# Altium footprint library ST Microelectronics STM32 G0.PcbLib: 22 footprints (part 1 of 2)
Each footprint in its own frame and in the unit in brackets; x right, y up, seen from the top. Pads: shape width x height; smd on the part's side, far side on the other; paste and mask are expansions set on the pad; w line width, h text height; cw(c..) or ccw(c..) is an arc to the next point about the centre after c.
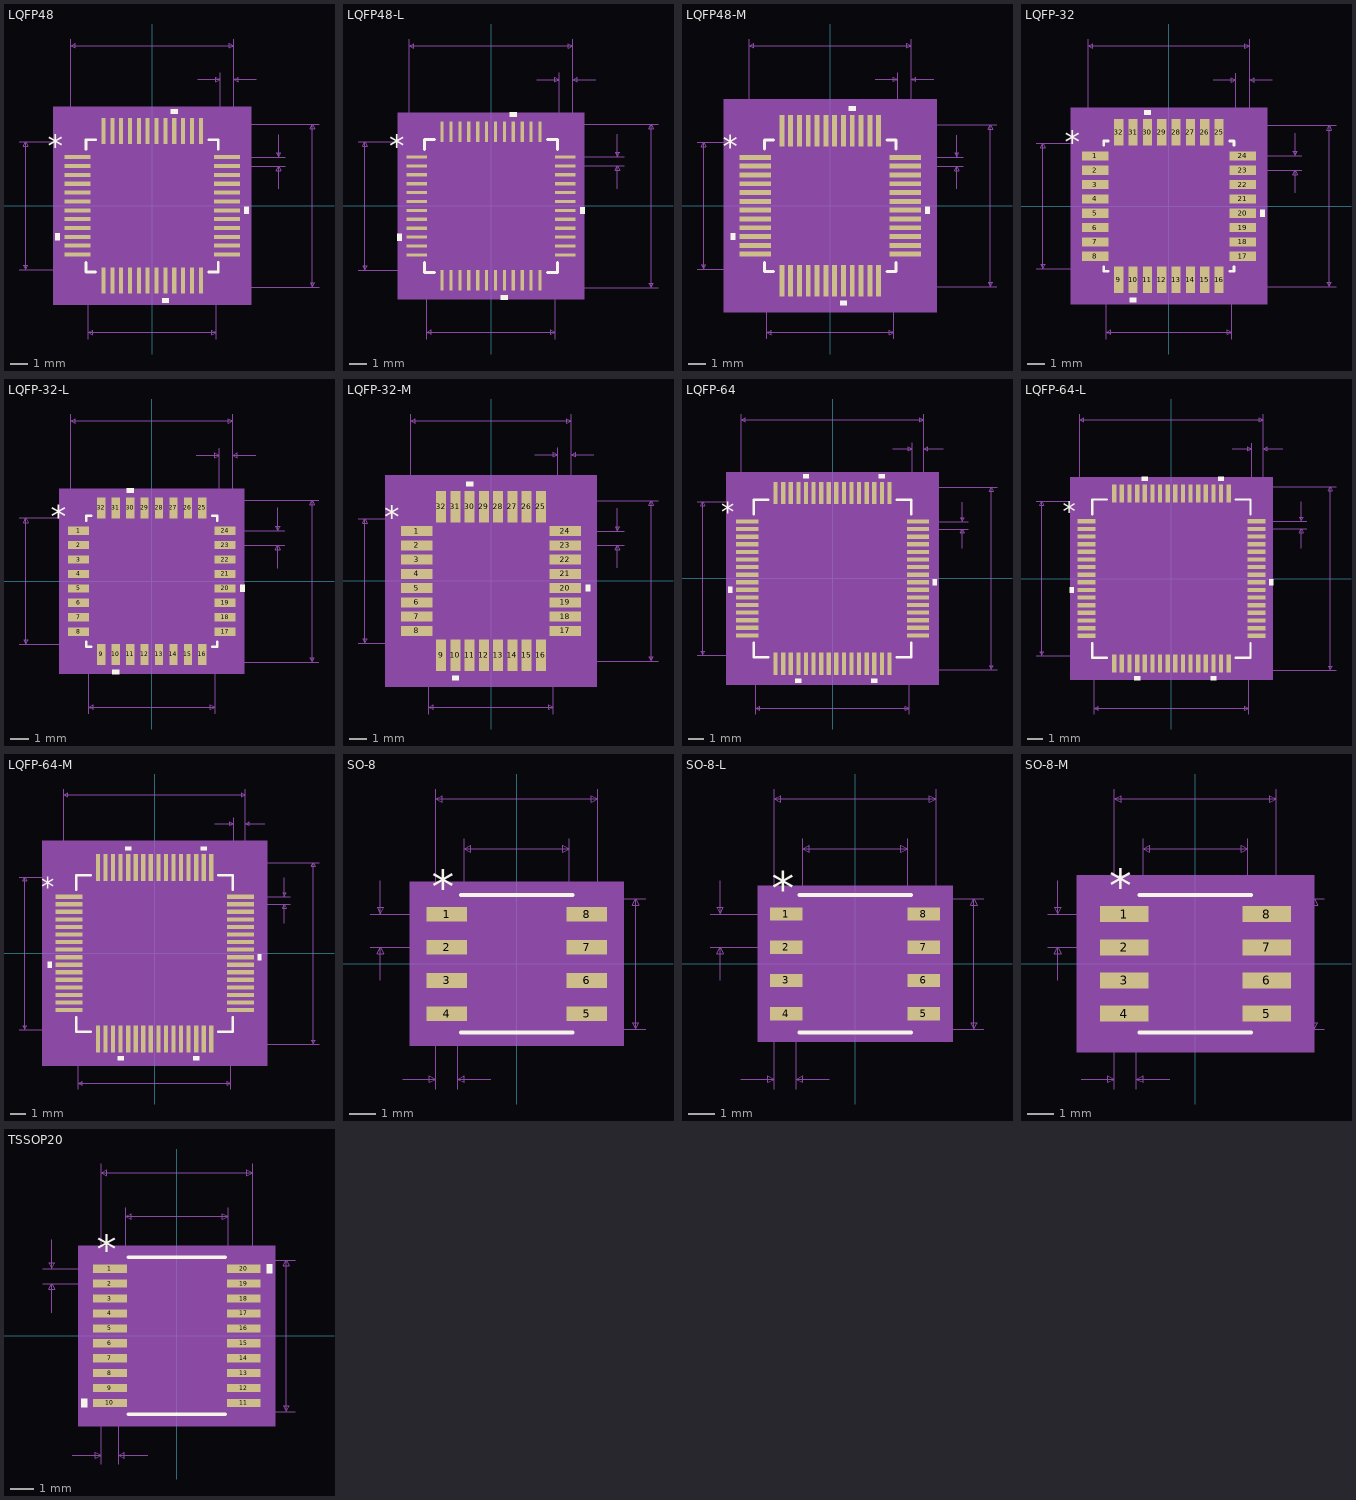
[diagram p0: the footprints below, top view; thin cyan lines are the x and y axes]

## LQFP48 [mil] "STM32 package, LQFP-48, 7 x 7mm"
pads (48):
  rect 58x9 smd paste+0 mask+0: 1(-166,108.27) 2(-166,88.58) 3(-166,68.9) 4(-166,49.21) 5(-166,29.53) 6(-166,9.84) 7(-166,-9.84) 8(-166,-29.53) 9(-166,-49.21) 10(-166,-68.9) 11(-166,-88.58) 12(-166,-108.27) 25(166,-108.27) 26(166,-88.58) 27(166,-68.9) 28(166,-49.21) 29(166,-29.53) 30(166,-9.84) 31(166,9.84) 32(166,29.53) 33(166,49.21) 34(166,68.9) 35(166,88.58) 36(166,108.27)
  rect 9x58 smd paste+0 mask+0: 13(-108.27,-166) 14(-88.58,-166) 15(-68.9,-166) 16(-49.21,-166) 17(-29.53,-166) 18(-9.84,-166) 19(9.84,-166) 20(29.53,-166) 21(49.21,-166) 22(68.9,-166) 23(88.58,-166) 24(108.27,-166) 37(108.27,166) 38(88.58,166) 39(68.9,166) 40(49.21,166) 41(29.53,166) 42(9.84,166) 43(-9.84,166) 44(-29.53,166) 45(-49.21,166) 46(-68.9,166) 47(-88.58,166) 48(-108.27,166)
Top Overlay:
  region: -205,-61.4 -215,-61.4 -215,-76.4 -205,-76.4
  region: 37.03,-205 22.03,-205 22.03,-215 37.03,-215
  region: 205,-2.34 215,-2.34 215,-17.34 205,-17.34
  region: 56.71,205 41.71,205 41.71,215 56.71,215
  lines w6: -147,-125.87 -147,-147 -125.87,-147 ; -147,125.87 -147,147 -125.87,147 ; 125.87,-147 147,-147 147,-125.87 ; 125.87,147 147,147 147,125.87
  text "*" at -232.5,108.11 h50
Mechanical 5:
  region: 220,-220 -220,-220 -220,220 220,220
Mechanical 7:
  lines w1: -296,-142 -108.27,-142 ; -296,142 -108.27,142 ; -181,108.27 -181,371 ; -142,-296 -142,-108.27 ; 101,281 151,281 ; 108.27,-181 371,-181 ; 108.27,181 371,181 ; 142,-296 142,-108.27 ; 151,108.27 151,296 ; 166,88.58 296,88.58 ; 166,108.27 296,108.27 ; 181,296 181,108.27 181,371 ; 231,281 181,281 ; 281,38.58 281,88.58 ; 281,158.27 281,108.27 ; -281,-142 -281,142 ; -281,-142 -286,-132 -276,-132 -281,-142 ; -281,142 -286,132 -276,132 -281,142 ; -181,356 181,356 ; -181,356 -171,361 -171,351 -181,356 ; -142,-281 142,-281 ; -142,-281 -132,-276 -132,-286 -142,-281 ; 142,-281 132,-276 132,-286 142,-281 ; 151,281 141,286 141,276 151,281 ; 181,281 191,286 191,276 181,281 ; 181,356 171,361 171,351 181,356 ; 281,88.58 276,78.58 286,78.58 281,88.58 ; 281,108.27 276,118.27 286,118.27 281,108.27 ; 356,-181 356,181 ; 356,-181 351,-171 361,-171 356,-181 ; 356,181 351,171 361,171 356,181
  text "Default Horiz Padstyle: RX9Y58D0T" at -412.5,-431 h50
  text "Default Vert Padstyle: RX9Y58D0T" at -400,-491 h50
  text "Alt 1 Padstyle: OX60Y90D30P" at -337.5,-671 h50
  text "Alt 2 Padstyle: OX90Y60D30P" at -337.5,-731 h50
  text "0.02in/0.5mm" at 301,85.93 h25
  text "0.03in/0.762mm" at 78.5,301 h25
  text "0.362in/9.195mm" at -93.75,376 h25
  text "0.284in/7.214mm" at -93.75,-326 h25
  text "0.284in/7.214mm" at -488.5,-12.5 h25
  text "0.362in/9.195mm" at 376,-12.5 h25
Mechanical 13:
  drawing of 197 lines, arcs and shapes, not listed
  text "*" at -139.5,93.11 h50
Mechanical 15:
  region: -122.77,-152 -152,-152 -152,-122.77 -205,-122.77 -205,122.77 -152,122.77 -152,152 -122.77,152 -122.77,205 122.77,205 122.77,152 152,152 152,122.77 205,122.77 205,-122.77 152,-122.77 152,-152 122.77,-152 122.77,-205 -122.77,-205
  lines w6: -205,-122.77 -152,-122.77 -152,-152 -122.77,-152 -122.77,-205 122.77,-205 122.77,-152 152,-152 152,-122.77 205,-122.77 205,122.77 152,122.77 152,152 122.77,152 122.77,205 -122.77,205 -122.77,152 -152,152 -152,122.77 -205,122.77 -205,-122.77
3D body "LQFP48.step": height 63.11, standoff 0, extent -180.98,-180.98 180.99,180.99
3D body: height 10, standoff 0, extent 0,0 10,10

## LQFP48-L [mil] "STM32 package, LQFP-48, 7 x 7mm"
pads (48):
  rect 46x7 smd paste+0 mask+0: 1(-164,108.27) 2(-164,88.58) 3(-164,68.9) 4(-164,49.21) 5(-164,29.53) 6(-164,9.84) 7(-164,-9.84) 8(-164,-29.53) 9(-164,-49.21) 10(-164,-68.9) 11(-164,-88.58) 12(-164,-108.27) 25(164,-108.27) 26(164,-88.58) 27(164,-68.9) 28(164,-49.21) 29(164,-29.53) 30(164,-9.84) 31(164,9.84) 32(164,29.53) 33(164,49.21) 34(164,68.9) 35(164,88.58) 36(164,108.27)
  rect 7x46 smd paste+0 mask+0: 13(-108.27,-164) 14(-88.58,-164) 15(-68.9,-164) 16(-49.21,-164) 17(-29.53,-164) 18(-9.84,-164) 19(9.84,-164) 20(29.53,-164) 21(49.21,-164) 22(68.9,-164) 23(88.58,-164) 24(108.27,-164) 37(108.27,164) 38(88.58,164) 39(68.9,164) 40(49.21,164) 41(29.53,164) 42(9.84,164) 43(-9.84,164) 44(-29.53,164) 45(-49.21,164) 46(-68.9,164) 47(-88.58,164) 48(-108.27,164)
Top Overlay:
  region: -197,-61.4 -207,-61.4 -207,-76.4 -197,-76.4
  region: 37.03,-197 22.03,-197 22.03,-207 37.03,-207
  region: 197,-2.34 207,-2.34 207,-17.34 197,-17.34
  region: 56.71,197 41.71,197 41.71,207 56.71,207
  lines w6: -147,-124.87 -147,-147 -124.87,-147 ; -147,124.87 -147,147 -124.87,147 ; 124.87,-147 147,-147 147,-124.87 ; 124.87,147 147,147 147,124.87
  text "*" at -224.5,108.11 h50
Mechanical 5:
  region: 206,-206 -206,-206 -206,206 206,206
Mechanical 7:
  lines w1: -294,-142 -108.27,-142 ; -294,142 -108.27,142 ; -181,108.27 -181,369 ; -142,-294 -142,-108.27 ; 101,279 151,279 ; 108.27,-181 369,-181 ; 108.27,181 369,181 ; 142,-294 142,-108.27 ; 151,108.27 151,294 ; 164,88.58 294,88.58 ; 164,108.27 294,108.27 ; 181,294 181,108.27 181,369 ; 231,279 181,279 ; 279,38.58 279,88.58 ; 279,158.27 279,108.27 ; -279,-142 -279,142 ; -279,-142 -284,-132 -274,-132 -279,-142 ; -279,142 -284,132 -274,132 -279,142 ; -181,354 181,354 ; -181,354 -171,359 -171,349 -181,354 ; -142,-279 142,-279 ; -142,-279 -132,-274 -132,-284 -142,-279 ; 142,-279 132,-274 132,-284 142,-279 ; 151,279 141,284 141,274 151,279 ; 181,279 191,284 191,274 181,279 ; 181,354 171,359 171,349 181,354 ; 279,88.58 274,78.58 284,78.58 279,88.58 ; 279,108.27 274,118.27 284,118.27 279,108.27 ; 354,-181 354,181 ; 354,-181 349,-171 359,-171 354,-181 ; 354,181 349,171 359,171 354,181
  text "Default Horiz Padstyle: RX7Y46D0T" at -412.5,-429 h50
  text "Default Vert Padstyle: RX7Y46D0T" at -400,-489 h50
  text "Alt 1 Padstyle: OX60Y90D30P" at -337.5,-669 h50
  text "Alt 2 Padstyle: OX90Y60D30P" at -337.5,-729 h50
  text "0.02in/0.5mm" at 299,85.93 h25
  text "0.03in/0.762mm" at 78.5,299 h25
  text "0.362in/9.195mm" at -93.75,374 h25
  text "0.284in/7.214mm" at -93.75,-324 h25
  text "0.284in/7.214mm" at -486.5,-12.5 h25
  text "0.362in/9.195mm" at 374,-12.5 h25
Mechanical 13:
  drawing of 197 lines, arcs and shapes, not listed
  text "*" at -139.5,93.11 h50
Mechanical 15:
  region: -115.77,-146 -146,-146 -146,-115.77 -191,-115.77 -191,115.77 -146,115.77 -146,146 -115.77,146 -115.77,191 115.77,191 115.77,146 146,146 146,115.77 191,115.77 191,-115.77 146,-115.77 146,-146 115.77,-146 115.77,-191 -115.77,-191
  lines w6: -191,-115.77 -146,-115.77 -146,-146 -115.77,-146 -115.77,-191 115.77,-191 115.77,-146 146,-146 146,-115.77 191,-115.77 191,115.77 146,115.77 146,146 115.77,146 115.77,191 -115.77,191 -115.77,146 -146,146 -146,115.77 -191,115.77 -191,-115.77
3D body "LQFP48-L.step": height 63.11, standoff 0, extent -180.98,-180.98 180.99,180.99
3D body: height 10, standoff 0, extent 0,0 10,10

## LQFP48-M [mil] "STM32 package, LQFP-48, 7 x 7mm"
pads (48):
  rect 70x11 smd paste+0 mask+0: 1(-168,108.27) 2(-168,88.58) 3(-168,68.9) 4(-168,49.21) 5(-168,29.53) 6(-168,9.84) 7(-168,-9.84) 8(-168,-29.53) 9(-168,-49.21) 10(-168,-68.9) 11(-168,-88.58) 12(-168,-108.27) 25(168,-108.27) 26(168,-88.58) 27(168,-68.9) 28(168,-49.21) 29(168,-29.53) 30(168,-9.84) 31(168,9.84) 32(168,29.53) 33(168,49.21) 34(168,68.9) 35(168,88.58) 36(168,108.27)
  rect 11x70 smd paste+0 mask+0: 13(-108.27,-168) 14(-88.58,-168) 15(-68.9,-168) 16(-49.21,-168) 17(-29.53,-168) 18(-9.84,-168) 19(9.84,-168) 20(29.53,-168) 21(49.21,-168) 22(68.9,-168) 23(88.58,-168) 24(108.27,-168) 37(108.27,168) 38(88.58,168) 39(68.9,168) 40(49.21,168) 41(29.53,168) 42(9.84,168) 43(-9.84,168) 44(-29.53,168) 45(-49.21,168) 46(-68.9,168) 47(-88.58,168) 48(-108.27,168)
Top Overlay:
  region: -213,-61.4 -223,-61.4 -223,-76.4 -213,-76.4
  region: 37.03,-213 22.03,-213 22.03,-223 37.03,-223
  region: 213,-2.34 223,-2.34 223,-17.34 213,-17.34
  region: 56.71,213 41.71,213 41.71,223 56.71,223
  lines w6: -147,-126.87 -147,-147 -126.87,-147 ; -147,126.87 -147,147 -126.87,147 ; 126.87,-147 147,-147 147,-126.87 ; 126.87,147 147,147 147,126.87
  text "*" at -240.5,108.11 h50
Mechanical 5:
  region: 238,-238 -238,-238 -238,238 238,238
Mechanical 7:
  lines w1: -298,-142 -108.27,-142 ; -298,142 -108.27,142 ; -181,108.27 -181,373 ; -142,-298 -142,-108.27 ; 101,283 151,283 ; 108.27,-181 373,-181 ; 108.27,181 373,181 ; 142,-298 142,-108.27 ; 151,108.27 151,298 ; 168,88.58 298,88.58 ; 168,108.27 298,108.27 ; 181,298 181,108.27 181,373 ; 231,283 181,283 ; 283,38.58 283,88.58 ; 283,158.27 283,108.27 ; -283,-142 -283,142 ; -283,-142 -288,-132 -278,-132 -283,-142 ; -283,142 -288,132 -278,132 -283,142 ; -181,358 181,358 ; -181,358 -171,363 -171,353 -181,358 ; -142,-283 142,-283 ; -142,-283 -132,-278 -132,-288 -142,-283 ; 142,-283 132,-278 132,-288 142,-283 ; 151,283 141,288 141,278 151,283 ; 181,283 191,288 191,278 181,283 ; 181,358 171,363 171,353 181,358 ; 283,88.58 278,78.58 288,78.58 283,88.58 ; 283,108.27 278,118.27 288,118.27 283,108.27 ; 358,-181 358,181 ; 358,-181 353,-171 363,-171 358,-181 ; 358,181 353,171 363,171 358,181
  text "Default Horiz Padstyle: RX11Y70D0T" at -425,-433 h50
  text "Default Vert Padstyle: RX11Y70D0T" at -412.5,-493 h50
  text "Alt 1 Padstyle: OX60Y90D30P" at -337.5,-673 h50
  text "Alt 2 Padstyle: OX90Y60D30P" at -337.5,-733 h50
  text "0.02in/0.5mm" at 303,85.93 h25
  text "0.03in/0.762mm" at 78.5,303 h25
  text "0.362in/9.195mm" at -93.75,378 h25
  text "0.284in/7.214mm" at -93.75,-328 h25
  text "0.284in/7.214mm" at -490.5,-12.5 h25
  text "0.362in/9.195mm" at 378,-12.5 h25
Mechanical 13:
  drawing of 197 lines, arcs and shapes, not listed
  text "*" at -139.5,93.11 h50
Mechanical 15:
  region: -133.77,-162 -162,-162 -162,-133.77 -223,-133.77 -223,133.77 -162,133.77 -162,162 -133.77,162 -133.77,223 133.77,223 133.77,162 162,162 162,133.77 223,133.77 223,-133.77 162,-133.77 162,-162 133.77,-162 133.77,-223 -133.77,-223
  lines w6: -223,-133.77 -162,-133.77 -162,-162 -133.77,-162 -133.77,-223 133.77,-223 133.77,-162 162,-162 162,-133.77 223,-133.77 223,133.77 162,133.77 162,162 133.77,162 133.77,223 -133.77,223 -133.77,162 -162,162 -162,133.77 -223,133.77 -223,-133.77
3D body: height 10, standoff 0, extent 0,0 10,10
3D body "LQFP48-M.step": height 63.11, standoff 0, extent -180.98,-180.98 180.99,180.99

## LQFP-32 [mil] "STM32 package, LQFP-32, 7 x 7mm"
pads (32):
  rect 58x20 smd paste+0 mask+0: 1(-162,110.24) 2(-162,78.74) 3(-162,47.24) 4(-162,15.75) 5(-162,-15.75) 6(-162,-47.24) 7(-162,-78.74) 8(-162,-110.24) 17(162,-110.24) 18(162,-78.74) 19(162,-47.24) 20(162,-15.75) 21(162,15.75) 22(162,47.24) 23(162,78.74) 24(162,110.24)
  rect 20x58 smd paste+0 mask+0: 9(-110.24,-162) 10(-78.74,-162) 11(-47.24,-162) 12(-15.75,-162) 13(15.75,-162) 14(47.24,-162) 15(78.74,-162) 16(110.24,-162) 25(110.24,162) 26(78.74,162) 27(47.24,162) 28(15.75,162) 29(-15.75,162) 30(-47.24,162) 31(-78.74,162) 32(-110.24,162)
Top Overlay:
  region: -71.24,-201 -86.24,-201 -86.24,-211 -71.24,-211
  region: 201,-8.25 211,-8.25 211,-23.25 201,-23.25
  region: -39.74,201 -54.74,201 -54.74,211 -39.74,211
  lines w6: -143,-133.34 -143,-143 -133.34,-143 ; -143,133.34 -143,143 -133.34,143 ; 133.34,-143 143,-143 143,-133.34 ; 133.34,143 143,143 143,133.34
  text "*" at -228.5,115.98 h50
Mechanical 5:
  region: 216,-216 -216,-216 -216,216 216,216
Mechanical 7:
  lines w1: -292,-138 -110.24,-138 ; -292,138 -110.24,138 ; -177,110.24 -177,367 ; -138,-292 -138,-110.24 ; 97,277 147,277 ; 110.24,-177 367,-177 ; 110.24,177 367,177 ; 138,-292 138,-110.24 ; 147,110.24 147,292 ; 162,78.74 292,78.74 ; 162,110.24 292,110.24 ; 177,292 177,110.24 177,367 ; 227,277 177,277 ; 277,28.74 277,78.74 ; 277,160.24 277,110.24 ; -277,-138 -277,138 ; -277,-138 -282,-128 -272,-128 -277,-138 ; -277,138 -282,128 -272,128 -277,138 ; -177,352 177,352 ; -177,352 -167,357 -167,347 -177,352 ; -138,-277 138,-277 ; -138,-277 -128,-272 -128,-282 -138,-277 ; 138,-277 128,-272 128,-282 138,-277 ; 147,277 137,282 137,272 147,277 ; 177,277 187,282 187,272 177,277 ; 177,352 167,357 167,347 177,352 ; 277,78.74 272,68.74 282,68.74 277,78.74 ; 277,110.24 272,120.24 282,120.24 277,110.24 ; 352,-177 352,177 ; 352,-177 347,-167 357,-167 352,-177 ; 352,177 347,167 357,167 352,177
  text "Default Horiz Padstyle: RX20Y58D0T" at -425,-427 h50
  text "Default Vert Padstyle: RX20Y58D0T" at -412.5,-487 h50
  text "Alt 1 Padstyle: OX60Y90D30P" at -337.5,-667 h50
  text "Alt 2 Padstyle: OX90Y60D30P" at -337.5,-727 h50
  text "0.031in/0.8mm" at 297,81.99 h25
  text "0.03in/0.762mm" at 74.5,297 h25
  text "0.354in/8.992mm" at -93.75,372 h25
  text "0.276in/7.01mm" at -87.5,-322 h25
  text "0.276in/7.01mm" at -472,-12.5 h25
  text "0.354in/8.992mm" at 372,-12.5 h25
Mechanical 13:
  lines w1: -138,88 -88,138 ; -177,-119.24 -177,-101.24 -138,-101.24 -138,-119.24 -177,-119.24 ; -177,-87.74 -177,-69.74 -138,-69.74 -138,-87.74 -177,-87.74 ; -177,-56.24 -177,-38.24 -138,-38.24 -138,-56.24 -177,-56.24 ; -177,-24.75 -177,-6.75 -138,-6.75 -138,-24.75 -177,-24.75 ; -177,6.75 -177,24.75 -138,24.75 -138,6.75 -177,6.75 ; -177,38.24 -177,56.24 -138,56.24 -138,38.24 -177,38.24 ; -177,69.74 -177,87.74 -138,87.74 -138,69.74 -177,69.74 ; -177,101.24 -177,119.24 -138,119.24 -138,101.24 -177,101.24 ; -138,-138 138,-138 138,138 -138,138 -138,-138 ; -119.24,-177 -119.24,-138 -101.24,-138 -101.24,-177 -119.24,-177 ; -119.24,138 -101.24,138 -101.24,177 -119.24,177 -119.24,138 ; -87.74,-177 -87.74,-138 -69.74,-138 -69.74,-177 -87.74,-177 ; -87.74,138 -69.74,138 -69.74,177 -87.74,177 -87.74,138 ; -56.24,-177 -56.24,-138 -38.24,-138 -38.24,-177 -56.24,-177 ; -56.24,138 -38.24,138 -38.24,177 -56.24,177 -56.24,138 ; -24.75,-177 -24.75,-138 -6.75,-138 -6.75,-177 -24.75,-177 ; -24.75,138 -6.75,138 -6.75,177 -24.75,177 -24.75,138 ; 6.75,-177 6.75,-138 24.75,-138 24.75,-177 6.75,-177 ; 6.75,138 24.75,138 24.75,177 6.75,177 6.75,138 ; 38.24,-177 38.24,-138 56.24,-138 56.24,-177 38.24,-177 ; 38.24,138 56.24,138 56.24,177 38.24,177 38.24,138 ; 69.74,-177 69.74,-138 87.74,-138 87.74,-177 69.74,-177 ; 69.74,138 87.74,138 87.74,177 69.74,177 69.74,138 ; 101.24,-177 101.24,-138 119.24,-138 119.24,-177 101.24,-177 ; 101.24,138 119.24,138 119.24,177 101.24,177 101.24,138 ; 138,-119.24 138,-101.24 177,-101.24 177,-119.24 138,-119.24 ; 138,-87.74 138,-69.74 177,-69.74 177,-87.74 138,-87.74 ; 138,-56.24 138,-38.24 177,-38.24 177,-56.24 138,-56.24 ; 138,-24.75 138,-6.75 177,-6.75 177,-24.75 138,-24.75 ; 138,6.75 138,24.75 177,24.75 177,6.75 138,6.75 ; 138,38.24 138,56.24 177,56.24 177,38.24 138,38.24 ; 138,69.74 138,87.74 177,87.74 177,69.74 138,69.74 ; 138,101.24 138,119.24 177,119.24 177,101.24 138,101.24
  text "*" at -135.5,100.98 h50
Mechanical 15:
  region: -130.24,-148 -148,-148 -148,-130.24 -201,-130.24 -201,130.24 -148,130.24 -148,148 -130.24,148 -130.24,201 130.24,201 130.24,148 148,148 148,130.24 201,130.24 201,-130.24 148,-130.24 148,-148 130.24,-148 130.24,-201 -130.24,-201
  lines w6: -201,-130.24 -148,-130.24 -148,-148 -130.24,-148 -130.24,-201 130.24,-201 130.24,-148 148,-148 148,-130.24 201,-130.24 201,130.24 148,130.24 148,148 130.24,148 130.24,201 -130.24,201 -130.24,148 -148,148 -148,130.24 -201,130.24 -201,-130.24
3D body: height 10, standoff 0, extent 0,0 10,10
3D body "LQFP-32.step": height 63.11, standoff 0, extent -177,-177 177.01,177.01

## LQFP-32-L [mil] "STM32 package, LQFP-32, 7 x 7mm"
pads (32):
  rect 46x18 smd paste+0 mask+0: 1(-160,110.24) 2(-160,78.74) 3(-160,47.24) 4(-160,15.75) 5(-160,-15.75) 6(-160,-47.24) 7(-160,-78.74) 8(-160,-110.24) 17(160,-110.24) 18(160,-78.74) 19(160,-47.24) 20(160,-15.75) 21(160,15.75) 22(160,47.24) 23(160,78.74) 24(160,110.24)
  rect 18x46 smd paste+0 mask+0: 9(-110.24,-160) 10(-78.74,-160) 11(-47.24,-160) 12(-15.75,-160) 13(15.75,-160) 14(47.24,-160) 15(78.74,-160) 16(110.24,-160) 25(110.24,160) 26(78.74,160) 27(47.24,160) 28(15.75,160) 29(-15.75,160) 30(-47.24,160) 31(-78.74,160) 32(-110.24,160)
Top Overlay:
  region: -71.24,-193 -86.24,-193 -86.24,-203 -71.24,-203
  region: 193,-8.25 203,-8.25 203,-23.25 193,-23.25
  region: -39.74,193 -54.74,193 -54.74,203 -39.74,203
  lines w6: -143,-132.34 -143,-143 -132.34,-143 ; -143,132.34 -143,143 -132.34,143 ; 132.34,-143 143,-143 143,-132.34 ; 132.34,143 143,143 143,132.34
  text "*" at -220.5,115.98 h50
Mechanical 5:
  region: 202,-202 -202,-202 -202,202 202,202
Mechanical 7:
  lines w1: -290,-138 -110.24,-138 ; -290,138 -110.24,138 ; -177,110.24 -177,365 ; -138,-290 -138,-110.24 ; 97,275 147,275 ; 110.24,-177 365,-177 ; 110.24,177 365,177 ; 138,-290 138,-110.24 ; 147,110.24 147,290 ; 160,78.74 290,78.74 ; 160,110.24 290,110.24 ; 177,290 177,110.24 177,365 ; 227,275 177,275 ; 275,28.74 275,78.74 ; 275,160.24 275,110.24 ; -275,-138 -275,138 ; -275,-138 -280,-128 -270,-128 -275,-138 ; -275,138 -280,128 -270,128 -275,138 ; -177,350 177,350 ; -177,350 -167,355 -167,345 -177,350 ; -138,-275 138,-275 ; -138,-275 -128,-270 -128,-280 -138,-275 ; 138,-275 128,-270 128,-280 138,-275 ; 147,275 137,280 137,270 147,275 ; 177,275 187,280 187,270 177,275 ; 177,350 167,355 167,345 177,350 ; 275,78.74 270,68.74 280,68.74 275,78.74 ; 275,110.24 270,120.24 280,120.24 275,110.24 ; 350,-177 350,177 ; 350,-177 345,-167 355,-167 350,-177 ; 350,177 345,167 355,167 350,177
  text "Default Horiz Padstyle: RX18Y46D0T" at -425,-425 h50
  text "Default Vert Padstyle: RX18Y46D0T" at -412.5,-485 h50
  text "Alt 1 Padstyle: OX60Y90D30P" at -337.5,-665 h50
  text "Alt 2 Padstyle: OX90Y60D30P" at -337.5,-725 h50
  text "0.031in/0.8mm" at 295,81.99 h25
  text "0.03in/0.762mm" at 74.5,295 h25
  text "0.354in/8.992mm" at -93.75,370 h25
  text "0.276in/7.01mm" at -87.5,-320 h25
  text "0.276in/7.01mm" at -470,-12.5 h25
  text "0.354in/8.992mm" at 370,-12.5 h25
Mechanical 13:
  lines w1: -138,88 -88,138 ; -177,-119.24 -177,-101.24 -138,-101.24 -138,-119.24 -177,-119.24 ; -177,-87.74 -177,-69.74 -138,-69.74 -138,-87.74 -177,-87.74 ; -177,-56.24 -177,-38.24 -138,-38.24 -138,-56.24 -177,-56.24 ; -177,-24.75 -177,-6.75 -138,-6.75 -138,-24.75 -177,-24.75 ; -177,6.75 -177,24.75 -138,24.75 -138,6.75 -177,6.75 ; -177,38.24 -177,56.24 -138,56.24 -138,38.24 -177,38.24 ; -177,69.74 -177,87.74 -138,87.74 -138,69.74 -177,69.74 ; -177,101.24 -177,119.24 -138,119.24 -138,101.24 -177,101.24 ; -138,-138 138,-138 138,138 -138,138 -138,-138 ; -119.24,-177 -119.24,-138 -101.24,-138 -101.24,-177 -119.24,-177 ; -119.24,138 -101.24,138 -101.24,177 -119.24,177 -119.24,138 ; -87.74,-177 -87.74,-138 -69.74,-138 -69.74,-177 -87.74,-177 ; -87.74,138 -69.74,138 -69.74,177 -87.74,177 -87.74,138 ; -56.24,-177 -56.24,-138 -38.24,-138 -38.24,-177 -56.24,-177 ; -56.24,138 -38.24,138 -38.24,177 -56.24,177 -56.24,138 ; -24.75,-177 -24.75,-138 -6.75,-138 -6.75,-177 -24.75,-177 ; -24.75,138 -6.75,138 -6.75,177 -24.75,177 -24.75,138 ; 6.75,-177 6.75,-138 24.75,-138 24.75,-177 6.75,-177 ; 6.75,138 24.75,138 24.75,177 6.75,177 6.75,138 ; 38.24,-177 38.24,-138 56.24,-138 56.24,-177 38.24,-177 ; 38.24,138 56.24,138 56.24,177 38.24,177 38.24,138 ; 69.74,-177 69.74,-138 87.74,-138 87.74,-177 69.74,-177 ; 69.74,138 87.74,138 87.74,177 69.74,177 69.74,138 ; 101.24,-177 101.24,-138 119.24,-138 119.24,-177 101.24,-177 ; 101.24,138 119.24,138 119.24,177 101.24,177 101.24,138 ; 138,-119.24 138,-101.24 177,-101.24 177,-119.24 138,-119.24 ; 138,-87.74 138,-69.74 177,-69.74 177,-87.74 138,-87.74 ; 138,-56.24 138,-38.24 177,-38.24 177,-56.24 138,-56.24 ; 138,-24.75 138,-6.75 177,-6.75 177,-24.75 138,-24.75 ; 138,6.75 138,24.75 177,24.75 177,6.75 138,6.75 ; 138,38.24 138,56.24 177,56.24 177,38.24 138,38.24 ; 138,69.74 138,87.74 177,87.74 177,69.74 138,69.74 ; 138,101.24 138,119.24 177,119.24 177,101.24 138,101.24
  text "*" at -135.5,100.98 h50
Mechanical 15:
  region: -123.24,-142 -142,-142 -142,-123.24 -187,-123.24 -187,123.24 -142,123.24 -142,142 -123.24,142 -123.24,187 123.24,187 123.24,142 142,142 142,123.24 187,123.24 187,-123.24 142,-123.24 142,-142 123.24,-142 123.24,-187 -123.24,-187
  lines w6: -187,-123.24 -142,-123.24 -142,-142 -123.24,-142 -123.24,-187 123.24,-187 123.24,-142 142,-142 142,-123.24 187,-123.24 187,123.24 142,123.24 142,142 123.24,142 123.24,187 -123.24,187 -123.24,142 -142,142 -142,123.24 -187,123.24 -187,-123.24
3D body "LQFP-32-L.step": height 63.11, standoff 0, extent -177,-177 177.01,177.01
3D body: height 10, standoff 0, extent 0,0 10,10

## LQFP-32-M [mil] "STM32 package, LQFP-32, 7 x 7mm"
pads (32):
  rect 70x22 smd paste+0 mask+0: 1(-164,110.24) 2(-164,78.74) 3(-164,47.24) 4(-164,15.75) 5(-164,-15.75) 6(-164,-47.24) 7(-164,-78.74) 8(-164,-110.24) 17(164,-110.24) 18(164,-78.74) 19(164,-47.24) 20(164,-15.75) 21(164,15.75) 22(164,47.24) 23(164,78.74) 24(164,110.24)
  rect 22x70 smd paste+0 mask+0: 9(-110.24,-164) 10(-78.74,-164) 11(-47.24,-164) 12(-15.75,-164) 13(15.75,-164) 14(47.24,-164) 15(78.74,-164) 16(110.24,-164) 25(110.24,164) 26(78.74,164) 27(47.24,164) 28(15.75,164) 29(-15.75,164) 30(-47.24,164) 31(-78.74,164) 32(-110.24,164)
Top Overlay:
  region: -71.24,-209 -86.24,-209 -86.24,-219 -71.24,-219
  region: 209,-8.25 219,-8.25 219,-23.25 209,-23.25
  region: -39.74,209 -54.74,209 -54.74,219 -39.74,219
  text "*" at -236.5,115.98 h50
Mechanical 5:
  region: 234,-234 -234,-234 -234,234 234,234
Mechanical 7:
  lines w1: -294,-138 -110.24,-138 ; -294,138 -110.24,138 ; -177,110.24 -177,369 ; -138,-294 -138,-110.24 ; 97,279 147,279 ; 110.24,-177 369,-177 ; 110.24,177 369,177 ; 138,-294 138,-110.24 ; 147,110.24 147,294 ; 164,78.74 294,78.74 ; 164,110.24 294,110.24 ; 177,294 177,110.24 177,369 ; 227,279 177,279 ; 279,28.74 279,78.74 ; 279,160.24 279,110.24 ; -279,-138 -279,138 ; -279,-138 -284,-128 -274,-128 -279,-138 ; -279,138 -284,128 -274,128 -279,138 ; -177,354 177,354 ; -177,354 -167,359 -167,349 -177,354 ; -138,-279 138,-279 ; -138,-279 -128,-274 -128,-284 -138,-279 ; 138,-279 128,-274 128,-284 138,-279 ; 147,279 137,284 137,274 147,279 ; 177,279 187,284 187,274 177,279 ; 177,354 167,359 167,349 177,354 ; 279,78.74 274,68.74 284,68.74 279,78.74 ; 279,110.24 274,120.24 284,120.24 279,110.24 ; 354,-177 354,177 ; 354,-177 349,-167 359,-167 354,-177 ; 354,177 349,167 359,167 354,177
  text "Default Horiz Padstyle: RX22Y70D0T" at -425,-429 h50
  text "Default Vert Padstyle: RX22Y70D0T" at -412.5,-489 h50
  text "Alt 1 Padstyle: OX60Y90D30P" at -337.5,-669 h50
  text "Alt 2 Padstyle: OX90Y60D30P" at -337.5,-729 h50
  text "0.031in/0.8mm" at 299,81.99 h25
  text "0.03in/0.762mm" at 74.5,299 h25
  text "0.354in/8.992mm" at -93.75,374 h25
  text "0.276in/7.01mm" at -87.5,-324 h25
  text "0.276in/7.01mm" at -474,-12.5 h25
  text "0.354in/8.992mm" at 374,-12.5 h25
Mechanical 13:
  lines w1: -138,88 -88,138 ; -177,-119.24 -177,-101.24 -138,-101.24 -138,-119.24 -177,-119.24 ; -177,-87.74 -177,-69.74 -138,-69.74 -138,-87.74 -177,-87.74 ; -177,-56.24 -177,-38.24 -138,-38.24 -138,-56.24 -177,-56.24 ; -177,-24.75 -177,-6.75 -138,-6.75 -138,-24.75 -177,-24.75 ; -177,6.75 -177,24.75 -138,24.75 -138,6.75 -177,6.75 ; -177,38.24 -177,56.24 -138,56.24 -138,38.24 -177,38.24 ; -177,69.74 -177,87.74 -138,87.74 -138,69.74 -177,69.74 ; -177,101.24 -177,119.24 -138,119.24 -138,101.24 -177,101.24 ; -138,-138 138,-138 138,138 -138,138 -138,-138 ; -119.24,-177 -119.24,-138 -101.24,-138 -101.24,-177 -119.24,-177 ; -119.24,138 -101.24,138 -101.24,177 -119.24,177 -119.24,138 ; -87.74,-177 -87.74,-138 -69.74,-138 -69.74,-177 -87.74,-177 ; -87.74,138 -69.74,138 -69.74,177 -87.74,177 -87.74,138 ; -56.24,-177 -56.24,-138 -38.24,-138 -38.24,-177 -56.24,-177 ; -56.24,138 -38.24,138 -38.24,177 -56.24,177 -56.24,138 ; -24.75,-177 -24.75,-138 -6.75,-138 -6.75,-177 -24.75,-177 ; -24.75,138 -6.75,138 -6.75,177 -24.75,177 -24.75,138 ; 6.75,-177 6.75,-138 24.75,-138 24.75,-177 6.75,-177 ; 6.75,138 24.75,138 24.75,177 6.75,177 6.75,138 ; 38.24,-177 38.24,-138 56.24,-138 56.24,-177 38.24,-177 ; 38.24,138 56.24,138 56.24,177 38.24,177 38.24,138 ; 69.74,-177 69.74,-138 87.74,-138 87.74,-177 69.74,-177 ; 69.74,138 87.74,138 87.74,177 69.74,177 69.74,138 ; 101.24,-177 101.24,-138 119.24,-138 119.24,-177 101.24,-177 ; 101.24,138 119.24,138 119.24,177 101.24,177 101.24,138 ; 138,-119.24 138,-101.24 177,-101.24 177,-119.24 138,-119.24 ; 138,-87.74 138,-69.74 177,-69.74 177,-87.74 138,-87.74 ; 138,-56.24 138,-38.24 177,-38.24 177,-56.24 138,-56.24 ; 138,-24.75 138,-6.75 177,-6.75 177,-24.75 138,-24.75 ; 138,6.75 138,24.75 177,24.75 177,6.75 138,6.75 ; 138,38.24 138,56.24 177,56.24 177,38.24 138,38.24 ; 138,69.74 138,87.74 177,87.74 177,69.74 138,69.74 ; 138,101.24 138,119.24 177,119.24 177,101.24 138,101.24
  text "*" at -135.5,100.98 h50
Mechanical 15:
  region: -141.24,-158 -158,-158 -158,-141.24 -219,-141.24 -219,141.24 -158,141.24 -158,158 -141.24,158 -141.24,219 141.24,219 141.24,158 158,158 158,141.24 219,141.24 219,-141.24 158,-141.24 158,-158 141.24,-158 141.24,-219 -141.24,-219
  lines w6: -219,-141.24 -158,-141.24 -158,-158 -141.24,-158 -141.24,-219 141.24,-219 141.24,-158 158,-158 158,-141.24 219,-141.24 219,141.24 158,141.24 158,158 141.24,158 141.24,219 -141.24,219 -141.24,158 -158,158 -158,141.24 -219,141.24 -219,-141.24
3D body "LQFP-32-M.step": height 63.11, standoff 0, extent -177,-177 177.01,177.01
3D body: height 10, standoff 0, extent 0,0 10,10

## LQFP-64 [mil] "STM32 package, LQFP-64, 10 x 10mm"
pads (64):
  rect 58x11 smd paste+0 mask+0: 1(-221.5,147.64) 2(-221.5,127.95) 3(-221.5,108.27) 4(-221.5,88.58) 5(-221.5,68.9) 6(-221.5,49.21) 7(-221.5,29.53) 8(-221.5,9.84) 9(-221.5,-9.84) 10(-221.5,-29.53) 11(-221.5,-49.21) 12(-221.5,-68.9) 13(-221.5,-88.58) 14(-221.5,-108.27) 15(-221.5,-127.95) 16(-221.5,-147.64) 33(221.5,-147.64) 34(221.5,-127.95) 35(221.5,-108.27) 36(221.5,-88.58) 37(221.5,-68.9) 38(221.5,-49.21) 39(221.5,-29.53) 40(221.5,-9.84) 41(221.5,9.84) 42(221.5,29.53) 43(221.5,49.21) 44(221.5,68.9) 45(221.5,88.58) 46(221.5,108.27) 47(221.5,127.95) 48(221.5,147.64)
  rect 11x58 smd paste+0 mask+0: 17(-147.64,-221.5) 18(-127.95,-221.5) 19(-108.27,-221.5) 20(-88.58,-221.5) 21(-68.9,-221.5) 22(-49.21,-221.5) 23(-29.53,-221.5) 24(-9.84,-221.5) 25(9.84,-221.5) 26(29.53,-221.5) 27(49.21,-221.5) 28(68.9,-221.5) 29(88.58,-221.5) 30(108.27,-221.5) 31(127.95,-221.5) 32(147.64,-221.5) 49(147.64,221.5) 50(127.95,221.5) 51(108.27,221.5) 52(88.58,221.5) 53(68.9,221.5) 54(49.21,221.5) 55(29.53,221.5) 56(9.84,221.5) 57(-9.84,221.5) 58(-29.53,221.5) 59(-49.21,221.5) 60(-68.9,221.5) 61(-88.58,221.5) 62(-108.27,221.5) 63(-127.95,221.5) 64(-147.64,221.5)
Top Overlay:
  region: -61.4,260.5 -76.4,260.5 -76.4,270.5 -61.4,270.5
  region: 135.45,260.5 120.45,260.5 120.45,270.5 135.45,270.5
  region: 260.5,-2.34 270.5,-2.34 270.5,-17.34 260.5,-17.34
  region: 115.77,-260.5 100.77,-260.5 100.77,-270.5 115.77,-270.5
  region: -81.08,-260.5 -96.08,-260.5 -96.08,-270.5 -81.08,-270.5
  region: -260.5,-22.03 -270.5,-22.03 -270.5,-37.03 -260.5,-37.03
  lines w6: -204,-166.24 -204,-204 -166.24,-204 ; -204,166.24 -204,204 -166.24,204 ; 166.24,-204 204,-204 204,-166.24 ; 166.24,204 204,204 204,166.24
  text "*" at -288,147.48 h50
Mechanical 5:
  region: 275.5,-275.5 -275.5,-275.5 -275.5,275.5 275.5,275.5
Mechanical 7:
  lines w1: -351.5,-199 -147.64,-199 ; -351.5,199 -147.64,199 ; -236.5,147.64 -236.5,426.5 ; -199,-351.5 -199,-147.64 ; 147.64,-236.5 426.5,-236.5 ; 147.64,236.5 426.5,236.5 ; 156.5,336.5 206.5,336.5 ; 199,-351.5 199,-147.64 ; 206.5,147.64 206.5,351.5 ; 221.5,127.95 351.5,127.95 ; 221.5,147.64 351.5,147.64 ; 236.5,351.5 236.5,147.64 236.5,426.5 ; 286.5,336.5 236.5,336.5 ; 336.5,77.95 336.5,127.95 ; 336.5,197.64 336.5,147.64 ; -336.5,-199 -331.5,-189 -341.5,-189 -336.5,-199 ; -336.5,-199 -336.5,199 ; -336.5,199 -331.5,189 -341.5,189 -336.5,199 ; -236.5,411.5 -226.5,406.5 -226.5,416.5 -236.5,411.5 ; -236.5,411.5 236.5,411.5 ; -199,-336.5 -189,-341.5 -189,-331.5 -199,-336.5 ; -199,-336.5 199,-336.5 ; 199,-336.5 189,-341.5 189,-331.5 199,-336.5 ; 206.5,336.5 196.5,331.5 196.5,341.5 206.5,336.5 ; 236.5,336.5 246.5,331.5 246.5,341.5 236.5,336.5 ; 236.5,411.5 226.5,406.5 226.5,416.5 236.5,411.5 ; 336.5,127.95 341.5,117.95 331.5,117.95 336.5,127.95 ; 336.5,147.64 341.5,157.64 331.5,157.64 336.5,147.64 ; 411.5,-236.5 416.5,-226.5 406.5,-226.5 411.5,-236.5 ; 411.5,-236.5 411.5,236.5 ; 411.5,236.5 416.5,226.5 406.5,226.5 411.5,236.5
  text "0.473in/12.014mm" at 431.5,-12.5 h25
  text "0.398in/10.109mm" at -556.5,-12.5 h25
  text "0.398in/10.109mm" at -100,-381.5 h25
  text "0.473in/12.014mm" at -100,431.5 h25
  text "0.03in/0.762mm" at 134,356.5 h25
  text "0.02in/0.5mm" at 356.5,125.3 h25
  text "Alt 2 Padstyle: OX90Y60D30P" at -337.5,-786.5 h50
  text "Alt 1 Padstyle: OX60Y90D30P" at -337.5,-726.5 h50
  text "Default Vert Padstyle: RX11Y58D0T" at -412.5,-546.5 h50
  text "Default Horiz Padstyle: RX11Y58D0T" at -425,-486.5 h50
Mechanical 13:
  drawing of 261 lines, arcs and shapes, not listed
  text "*" at -196.5,132.48 h50
Mechanical 15:
  region: -163.14,-209 -209,-209 -209,-163.14 -260.5,-163.14 -260.5,163.14 -209,163.14 -209,209 -163.14,209 -163.14,260.5 163.14,260.5 163.14,209 209,209 209,163.14 260.5,163.14 260.5,-163.14 209,-163.14 209,-209 163.14,-209 163.14,-260.5 -163.14,-260.5
  lines w6: -260.5,-163.14 -260.5,163.14 -209,163.14 -209,209 -163.14,209 -163.14,260.5 163.14,260.5 163.14,209 209,209 209,163.14 260.5,163.14 260.5,-163.14 209,-163.14 209,-209 163.14,-209 163.14,-260.5 -163.14,-260.5 -163.14,-209 -209,-209 -209,-163.14 -260.5,-163.14
3D body "LQFP-64.step": height 63.11, standoff 0, extent -236.49,-236.49 236.5,236.5
3D body: height 10, standoff 0, extent 0,0 10,10

## LQFP-64-L [mil] "STM32 package, LQFP-64, 10 x 10mm"
pads (64):
  rect 46x11 smd paste+0 mask+0: 1(-219.5,147.64) 2(-219.5,127.95) 3(-219.5,108.27) 4(-219.5,88.58) 5(-219.5,68.9) 6(-219.5,49.21) 7(-219.5,29.53) 8(-219.5,9.84) 9(-219.5,-9.84) 10(-219.5,-29.53) 11(-219.5,-49.21) 12(-219.5,-68.9) 13(-219.5,-88.58) 14(-219.5,-108.27) 15(-219.5,-127.95) 16(-219.5,-147.64) 33(219.5,-147.64) 34(219.5,-127.95) 35(219.5,-108.27) 36(219.5,-88.58) 37(219.5,-68.9) 38(219.5,-49.21) 39(219.5,-29.53) 40(219.5,-9.84) 41(219.5,9.84) 42(219.5,29.53) 43(219.5,49.21) 44(219.5,68.9) 45(219.5,88.58) 46(219.5,108.27) 47(219.5,127.95) 48(219.5,147.64)
  rect 11x46 smd paste+0 mask+0: 17(-147.64,-219.5) 18(-127.95,-219.5) 19(-108.27,-219.5) 20(-88.58,-219.5) 21(-68.9,-219.5) 22(-49.21,-219.5) 23(-29.53,-219.5) 24(-9.84,-219.5) 25(9.84,-219.5) 26(29.53,-219.5) 27(49.21,-219.5) 28(68.9,-219.5) 29(88.58,-219.5) 30(108.27,-219.5) 31(127.95,-219.5) 32(147.64,-219.5) 49(147.64,219.5) 50(127.95,219.5) 51(108.27,219.5) 52(88.58,219.5) 53(68.9,219.5) 54(49.21,219.5) 55(29.53,219.5) 56(9.84,219.5) 57(-9.84,219.5) 58(-29.53,219.5) 59(-49.21,219.5) 60(-68.9,219.5) 61(-88.58,219.5) 62(-108.27,219.5) 63(-127.95,219.5) 64(-147.64,219.5)
Top Overlay:
  region: -61.4,252.5 -76.4,252.5 -76.4,262.5 -61.4,262.5
  region: 135.45,252.5 120.45,252.5 120.45,262.5 135.45,262.5
  region: 252.5,-2.34 262.5,-2.34 262.5,-17.34 252.5,-17.34
  region: 115.77,-252.5 100.77,-252.5 100.77,-262.5 115.77,-262.5
  region: -81.08,-252.5 -96.08,-252.5 -96.08,-262.5 -81.08,-262.5
  region: -252.5,-22.03 -262.5,-22.03 -262.5,-37.03 -252.5,-37.03
  lines w6: -204,-166.24 -204,-204 -166.24,-204 ; -204,166.24 -204,204 -166.24,204 ; 166.24,-204 204,-204 204,-166.24 ; 166.24,204 204,204 204,166.24
  text "*" at -280,147.48 h50
Mechanical 5:
  region: 261.5,-261.5 -261.5,-261.5 -261.5,261.5 261.5,261.5
Mechanical 7:
  lines w1: -349.5,-199 -147.64,-199 ; -349.5,199 -147.64,199 ; -236.5,147.64 -236.5,424.5 ; -199,-349.5 -199,-147.64 ; 147.64,-236.5 424.5,-236.5 ; 147.64,236.5 424.5,236.5 ; 156.5,334.5 206.5,334.5 ; 199,-349.5 199,-147.64 ; 206.5,147.64 206.5,349.5 ; 219.5,127.95 349.5,127.95 ; 219.5,147.64 349.5,147.64 ; 236.5,349.5 236.5,147.64 236.5,424.5 ; 286.5,334.5 236.5,334.5 ; 334.5,77.95 334.5,127.95 ; 334.5,197.64 334.5,147.64 ; -334.5,-199 -329.5,-189 -339.5,-189 -334.5,-199 ; -334.5,-199 -334.5,199 ; -334.5,199 -329.5,189 -339.5,189 -334.5,199 ; -236.5,409.5 -226.5,404.5 -226.5,414.5 -236.5,409.5 ; -236.5,409.5 236.5,409.5 ; -199,-334.5 -189,-339.5 -189,-329.5 -199,-334.5 ; -199,-334.5 199,-334.5 ; 199,-334.5 189,-339.5 189,-329.5 199,-334.5 ; 206.5,334.5 196.5,329.5 196.5,339.5 206.5,334.5 ; 236.5,334.5 246.5,329.5 246.5,339.5 236.5,334.5 ; 236.5,409.5 226.5,404.5 226.5,414.5 236.5,409.5 ; 334.5,127.95 339.5,117.95 329.5,117.95 334.5,127.95 ; 334.5,147.64 339.5,157.64 329.5,157.64 334.5,147.64 ; 409.5,-236.5 414.5,-226.5 404.5,-226.5 409.5,-236.5 ; 409.5,-236.5 409.5,236.5 ; 409.5,236.5 414.5,226.5 404.5,226.5 409.5,236.5
  text "0.473in/12.014mm" at 429.5,-12.5 h25
  text "0.398in/10.109mm" at -554.5,-12.5 h25
  text "0.398in/10.109mm" at -100,-379.5 h25
  text "0.473in/12.014mm" at -100,429.5 h25
  text "0.03in/0.762mm" at 134,354.5 h25
  text "0.02in/0.5mm" at 354.5,125.3 h25
  text "Alt 2 Padstyle: OX90Y60D30P" at -337.5,-784.5 h50
  text "Alt 1 Padstyle: OX60Y90D30P" at -337.5,-724.5 h50
  text "Default Vert Padstyle: RX11Y46D0T" at -412.5,-544.5 h50
  text "Default Horiz Padstyle: RX11Y46D0T" at -425,-484.5 h50
Mechanical 13:
  drawing of 261 lines, arcs and shapes, not listed
  text "*" at -196.5,132.48 h50
Mechanical 15:
  region: -157.14,-203 -203,-203 -203,-157.14 -246.5,-157.14 -246.5,157.14 -203,157.14 -203,203 -157.14,203 -157.14,246.5 157.14,246.5 157.14,203 203,203 203,157.14 246.5,157.14 246.5,-157.14 203,-157.14 203,-203 157.14,-203 157.14,-246.5 -157.14,-246.5
  lines w6: -246.5,-157.14 -246.5,157.14 -203,157.14 -203,203 -157.14,203 -157.14,246.5 157.14,246.5 157.14,203 203,203 203,157.14 246.5,157.14 246.5,-157.14 203,-157.14 203,-203 157.14,-203 157.14,-246.5 -157.14,-246.5 -157.14,-203 -203,-203 -203,-157.14 -246.5,-157.14
3D body "LQFP-64-L.step": height 63.11, standoff 0, extent -236.49,-236.49 236.5,236.5
3D body: height 10, standoff 0, extent 0,0 10,10

## LQFP-64-M [mil] "STM32 package, LQFP-64, 10 x 10mm"
pads (64):
  rect 70x11 smd paste+0 mask+0: 1(-223.5,147.64) 2(-223.5,127.95) 3(-223.5,108.27) 4(-223.5,88.58) 5(-223.5,68.9) 6(-223.5,49.21) 7(-223.5,29.53) 8(-223.5,9.84) 9(-223.5,-9.84) 10(-223.5,-29.53) 11(-223.5,-49.21) 12(-223.5,-68.9) 13(-223.5,-88.58) 14(-223.5,-108.27) 15(-223.5,-127.95) 16(-223.5,-147.64) 33(223.5,-147.64) 34(223.5,-127.95) 35(223.5,-108.27) 36(223.5,-88.58) 37(223.5,-68.9) 38(223.5,-49.21) 39(223.5,-29.53) 40(223.5,-9.84) 41(223.5,9.84) 42(223.5,29.53) 43(223.5,49.21) 44(223.5,68.9) 45(223.5,88.58) 46(223.5,108.27) 47(223.5,127.95) 48(223.5,147.64)
  rect 11x70 smd paste+0 mask+0: 17(-147.64,-223.5) 18(-127.95,-223.5) 19(-108.27,-223.5) 20(-88.58,-223.5) 21(-68.9,-223.5) 22(-49.21,-223.5) 23(-29.53,-223.5) 24(-9.84,-223.5) 25(9.84,-223.5) 26(29.53,-223.5) 27(49.21,-223.5) 28(68.9,-223.5) 29(88.58,-223.5) 30(108.27,-223.5) 31(127.95,-223.5) 32(147.64,-223.5) 49(147.64,223.5) 50(127.95,223.5) 51(108.27,223.5) 52(88.58,223.5) 53(68.9,223.5) 54(49.21,223.5) 55(29.53,223.5) 56(9.84,223.5) 57(-9.84,223.5) 58(-29.53,223.5) 59(-49.21,223.5) 60(-68.9,223.5) 61(-88.58,223.5) 62(-108.27,223.5) 63(-127.95,223.5) 64(-147.64,223.5)
Top Overlay:
  region: -61.4,268.5 -76.4,268.5 -76.4,278.5 -61.4,278.5
  region: 135.45,268.5 120.45,268.5 120.45,278.5 135.45,278.5
  region: 268.5,-2.34 278.5,-2.34 278.5,-17.34 268.5,-17.34
  region: 115.77,-268.5 100.77,-268.5 100.77,-278.5 115.77,-278.5
  region: -81.08,-268.5 -96.08,-268.5 -96.08,-278.5 -81.08,-278.5
  region: -268.5,-22.03 -278.5,-22.03 -278.5,-37.03 -268.5,-37.03
  lines w6: -204,-166.24 -204,-204 -166.24,-204 ; -204,166.24 -204,204 -166.24,204 ; 166.24,-204 204,-204 204,-166.24 ; 166.24,204 204,204 204,166.24
  text "*" at -296,147.48 h50
Mechanical 5:
  region: 293.5,-293.5 -293.5,-293.5 -293.5,293.5 293.5,293.5
Mechanical 7:
  lines w1: -353.5,-199 -147.64,-199 ; -353.5,199 -147.64,199 ; -236.5,147.64 -236.5,428.5 ; -199,-353.5 -199,-147.64 ; 147.64,-236.5 428.5,-236.5 ; 147.64,236.5 428.5,236.5 ; 156.5,338.5 206.5,338.5 ; 199,-353.5 199,-147.64 ; 206.5,147.64 206.5,353.5 ; 223.5,127.95 353.5,127.95 ; 223.5,147.64 353.5,147.64 ; 236.5,353.5 236.5,147.64 236.5,428.5 ; 286.5,338.5 236.5,338.5 ; 338.5,77.95 338.5,127.95 ; 338.5,197.64 338.5,147.64 ; -338.5,-199 -333.5,-189 -343.5,-189 -338.5,-199 ; -338.5,-199 -338.5,199 ; -338.5,199 -333.5,189 -343.5,189 -338.5,199 ; -236.5,413.5 -226.5,408.5 -226.5,418.5 -236.5,413.5 ; -236.5,413.5 236.5,413.5 ; -199,-338.5 -189,-343.5 -189,-333.5 -199,-338.5 ; -199,-338.5 199,-338.5 ; 199,-338.5 189,-343.5 189,-333.5 199,-338.5 ; 206.5,338.5 196.5,333.5 196.5,343.5 206.5,338.5 ; 236.5,338.5 246.5,333.5 246.5,343.5 236.5,338.5 ; 236.5,413.5 226.5,408.5 226.5,418.5 236.5,413.5 ; 338.5,127.95 343.5,117.95 333.5,117.95 338.5,127.95 ; 338.5,147.64 343.5,157.64 333.5,157.64 338.5,147.64 ; 413.5,-236.5 418.5,-226.5 408.5,-226.5 413.5,-236.5 ; 413.5,-236.5 413.5,236.5 ; 413.5,236.5 418.5,226.5 408.5,226.5 413.5,236.5
  text "0.473in/12.014mm" at 433.5,-12.5 h25
  text "0.398in/10.109mm" at -558.5,-12.5 h25
  text "0.398in/10.109mm" at -100,-383.5 h25
  text "0.473in/12.014mm" at -100,433.5 h25
  text "0.03in/0.762mm" at 134,358.5 h25
  text "0.02in/0.5mm" at 358.5,125.3 h25
  text "Alt 2 Padstyle: OX90Y60D30P" at -337.5,-788.5 h50
  text "Alt 1 Padstyle: OX60Y90D30P" at -337.5,-728.5 h50
  text "Default Vert Padstyle: RX11Y70D0T" at -412.5,-548.5 h50
  text "Default Horiz Padstyle: RX11Y70D0T" at -425,-488.5 h50
Mechanical 13:
  drawing of 261 lines, arcs and shapes, not listed
  text "*" at -196.5,132.48 h50
Mechanical 15:
  region: -173.14,-219 -219,-219 -219,-173.14 -278.5,-173.14 -278.5,173.14 -219,173.14 -219,219 -173.14,219 -173.14,278.5 173.14,278.5 173.14,219 219,219 219,173.14 278.5,173.14 278.5,-173.14 219,-173.14 219,-219 173.14,-219 173.14,-278.5 -173.14,-278.5
  lines w6: -278.5,-173.14 -278.5,173.14 -219,173.14 -219,219 -173.14,219 -173.14,278.5 173.14,278.5 173.14,219 219,219 219,173.14 278.5,173.14 278.5,-173.14 219,-173.14 219,-219 173.14,-219 173.14,-278.5 -173.14,-278.5 -173.14,-219 -219,-219 -219,-173.14 -278.5,-173.14
3D body: height 10, standoff 0, extent 0,0 10,10

## SO-8 [mil] "STM32 package, SO8N, 4.9 x 6mm"
pads (8):
  rect 61x22 smd paste+0 mask+0: 1(-105.5,75) 2(-105.5,25) 3(-105.5,-25) 4(-105.5,-75) 5(105.5,-75) 6(105.5,-25) 7(105.5,25) 8(105.5,75)
Top Overlay:
  lines w6: -84,-103.5 84,-103.5 ; -84,103.5 84,103.5
  text "*" at -128,92 h50
Mechanical 5:
  region: 161,-123.5 -161,-123.5 -161,123.5 161,123.5
Mechanical 7:
  lines w1: -220.5,25 -105.5,25 ; -220.5,75 -105.5,75 ; -205.5,-25 -205.5,25 ; -205.5,125 -205.5,75 ; -172,-173.5 -122,-173.5 ; -122,-188.5 -122,0 -122,263.5 ; -89,-188.5 -89,0 ; -79,0 -79,188.5 ; -39,-173.5 -89,-173.5 ; 0,-98.5 194,-98.5 ; 0,98.5 194,98.5 ; 79,0 79,188.5 ; 122,0 122,263.5 ; -205.5,25 -200.5,15 -210.5,15 -205.5,25 ; -205.5,75 -200.5,85 -210.5,85 -205.5,75 ; -122,-173.5 -132,-178.5 -132,-168.5 -122,-173.5 ; -122,248.5 -112,243.5 -112,253.5 -122,248.5 ; -122,248.5 122,248.5 ; -89,-173.5 -79,-178.5 -79,-168.5 -89,-173.5 ; -79,173.5 -69,168.5 -69,178.5 -79,173.5 ; -79,173.5 79,173.5 ; 79,173.5 69,168.5 69,178.5 79,173.5 ; 122,248.5 112,243.5 112,253.5 122,248.5 ; 179,-98.5 184,-88.5 174,-88.5 179,-98.5 ; 179,-98.5 179,98.5 ; 179,98.5 184,88.5 174,88.5 179,98.5
  text "0.033in/0.838mm" at -199.25,-218.5 h25
  text "0.05in/1.27mm" at -388,37.5 h25
  text "0.197in/5.004mm" at 199,-12.5 h25
  text "0.244in/6.198mm" at -93.75,268.5 h25
  text "0.158in/4.013mm" at -93.75,193.5 h25
  text "Alt 2 Padstyle: OX90Y60D30P" at -337.5,-598.5 h50
  text "Alt 1 Padstyle: OX60Y90D30P" at -337.5,-538.5 h50
  text "Pin One Padstyle: RX61Y22D0T" at -350,-358.5 h50
  text "Default Padstyle: RX61Y22D0T" at -350,-298.5 h50
Mechanical 13:
  lines w0: -12,98.5 ccw(c0,98.5) 12,98.5
  lines w1: -122,-85 -79,-85 -79,-65 -122,-65 -122,-85 ; -122,-35 -79,-35 -79,-15 -122,-15 -122,-35 ; -122,15 -79,15 -79,35 -122,35 -122,15 ; -122,65 -79,65 -79,85 -122,85 -122,65 ; -79,-98.5 -79,98.5 79,98.5 79,-98.5 -79,-98.5 ; 79,-85 122,-85 122,-65 79,-65 79,-85 ; 79,-35 122,-35 122,-15 79,-15 79,-35 ; 79,15 122,15 122,35 79,35 79,15 ; 79,65 122,65 122,85 79,85 79,65
  text "*" at -76.5,45.5 h50
Mechanical 15:
  region: -89,-96 -146,-96 -146,96 -89,96 -89,108.5 89,108.5 89,96 146,96 146,-96 89,-96 89,-108.5 -89,-108.5
  lines w6: -146,-96 -89,-96 -89,-108.5 89,-108.5 89,-96 146,-96 146,96 89,96 89,108.5 -89,108.5 -89,96 -146,96 -146,-96
3D body: height 10, standoff 0, extent 0,0 10,10
3D body "SO-8.step": height 69.09, standoff 0, extent -122,-98.5 122.01,98.51

## SO-8-L [mil] "STM32 package, SO8N, 4.9 x 6mm"
pads (8):
  rect 49x20 smd paste+0 mask+0: 1(-103.5,75) 2(-103.5,25) 3(-103.5,-25) 4(-103.5,-75) 5(103.5,-75) 6(103.5,-25) 7(103.5,25) 8(103.5,75)
Top Overlay:
  lines w6: -84,-103.5 84,-103.5 ; -84,103.5 84,103.5
  text "*" at -126,90 h50
Mechanical 5:
  region: 147,-117.5 -147,-117.5 -147,117.5 147,117.5
Mechanical 7:
  lines w1: -218.5,25 -103.5,25 ; -218.5,75 -103.5,75 ; -203.5,-25 -203.5,25 ; -203.5,125 -203.5,75 ; -172,-173.5 -122,-173.5 ; -122,-188.5 -122,0 -122,263.5 ; -89,-188.5 -89,0 ; -79,0 -79,188.5 ; -39,-173.5 -89,-173.5 ; 0,-98.5 194,-98.5 ; 0,98.5 194,98.5 ; 79,0 79,188.5 ; 122,0 122,263.5 ; -203.5,25 -198.5,15 -208.5,15 -203.5,25 ; -203.5,75 -198.5,85 -208.5,85 -203.5,75 ; -122,-173.5 -132,-178.5 -132,-168.5 -122,-173.5 ; -122,248.5 -112,243.5 -112,253.5 -122,248.5 ; -122,248.5 122,248.5 ; -89,-173.5 -79,-178.5 -79,-168.5 -89,-173.5 ; -79,173.5 -69,168.5 -69,178.5 -79,173.5 ; -79,173.5 79,173.5 ; 79,173.5 69,168.5 69,178.5 79,173.5 ; 122,248.5 112,243.5 112,253.5 122,248.5 ; 179,-98.5 184,-88.5 174,-88.5 179,-98.5 ; 179,-98.5 179,98.5 ; 179,98.5 184,88.5 174,88.5 179,98.5
  text "0.033in/0.838mm" at -199.25,-218.5 h25
  text "0.05in/1.27mm" at -386,37.5 h25
  text "0.197in/5.004mm" at 199,-12.5 h25
  text "0.244in/6.198mm" at -93.75,268.5 h25
  text "0.158in/4.013mm" at -93.75,193.5 h25
  text "Alt 2 Padstyle: OX90Y60D30P" at -337.5,-598.5 h50
  text "Alt 1 Padstyle: OX60Y90D30P" at -337.5,-538.5 h50
  text "Pin One Padstyle: RX49Y20D0T" at -350,-358.5 h50
  text "Default Padstyle: RX49Y20D0T" at -350,-298.5 h50
Mechanical 13:
  lines w0: -12,98.5 ccw(c0,98.5) 12,98.5
  lines w1: -122,-85 -79,-85 -79,-65 -122,-65 -122,-85 ; -122,-35 -79,-35 -79,-15 -122,-15 -122,-35 ; -122,15 -79,15 -79,35 -122,35 -122,15 ; -122,65 -79,65 -79,85 -122,85 -122,65 ; -79,-98.5 -79,98.5 79,98.5 79,-98.5 -79,-98.5 ; 79,-85 122,-85 122,-65 79,-65 79,-85 ; 79,-35 122,-35 122,-15 79,-15 79,-35 ; 79,15 122,15 122,35 79,35 79,15 ; 79,65 122,65 122,85 79,85 79,65
  text "*" at -76.5,45.5 h50
Mechanical 15:
  region: -83,-89 -132,-89 -132,89 -83,89 -83,102.5 83,102.5 83,89 132,89 132,-89 83,-89 83,-102.5 -83,-102.5
  lines w6: -132,-89 -83,-89 -83,-102.5 83,-102.5 83,-89 132,-89 132,89 83,89 83,102.5 -83,102.5 -83,89 -132,89 -132,-89
3D body: height 10, standoff 0, extent 0,0 10,10
3D body "SO-8-L.step": height 69.09, standoff 0, extent -122,-98.5 122.01,98.51

## SO-8-M [mil] "STM32 package, SO8N, 4.9 x 6mm"
pads (8):
  rect 73x24 smd paste+0 mask+0: 1(-107.5,75) 2(-107.5,25) 3(-107.5,-25) 4(-107.5,-75) 5(107.5,-75) 6(107.5,-25) 7(107.5,25) 8(107.5,75)
Top Overlay:
  lines w6: -84,-103.5 84,-103.5 ; -84,103.5 84,103.5
  text "*" at -130,94 h50
Mechanical 5:
  region: 179,-133.5 -179,-133.5 -179,133.5 179,133.5
Mechanical 7:
  lines w1: -222.5,25 -107.5,25 ; -222.5,75 -107.5,75 ; -207.5,-25 -207.5,25 ; -207.5,125 -207.5,75 ; -172,-173.5 -122,-173.5 ; -122,-188.5 -122,0 -122,263.5 ; -89,-188.5 -89,0 ; -79,0 -79,188.5 ; -39,-173.5 -89,-173.5 ; 0,-98.5 194,-98.5 ; 0,98.5 194,98.5 ; 79,0 79,188.5 ; 122,0 122,263.5 ; -207.5,25 -212.5,15 -202.5,15 -207.5,25 ; -207.5,75 -212.5,85 -202.5,85 -207.5,75 ; -122,-173.5 -132,-168.5 -132,-178.5 -122,-173.5 ; -122,248.5 122,248.5 ; -122,248.5 -112,253.5 -112,243.5 -122,248.5 ; -89,-173.5 -79,-168.5 -79,-178.5 -89,-173.5 ; -79,173.5 79,173.5 ; -79,173.5 -69,178.5 -69,168.5 -79,173.5 ; 79,173.5 69,178.5 69,168.5 79,173.5 ; 122,248.5 112,253.5 112,243.5 122,248.5 ; 179,-98.5 179,98.5 ; 179,-98.5 174,-88.5 184,-88.5 179,-98.5 ; 179,98.5 174,88.5 184,88.5 179,98.5
  text "Default Padstyle: RX73Y24D0T" at -350,-298.5 h50
  text "Pin One Padstyle: RX73Y24D0T" at -350,-358.5 h50
  text "Alt 1 Padstyle: OX60Y90D30P" at -337.5,-538.5 h50
  text "Alt 2 Padstyle: OX90Y60D30P" at -337.5,-598.5 h50
  text "0.158in/4.013mm" at -93.75,193.5 h25
  text "0.244in/6.198mm" at -93.75,268.5 h25
  text "0.197in/5.004mm" at 199,-12.5 h25
  text "0.05in/1.27mm" at -390,37.5 h25
  text "0.033in/0.838mm" at -199.25,-218.5 h25
Mechanical 13:
  lines w0: -12,98.5 ccw(c0,98.5) 12,98.5
  lines w1: -122,-85 -122,-65 -79,-65 -79,-85 -122,-85 ; -122,-35 -122,-15 -79,-15 -79,-35 -122,-35 ; -122,15 -122,35 -79,35 -79,15 -122,15 ; -122,65 -122,85 -79,85 -79,65 -122,65 ; -79,-98.5 79,-98.5 79,98.5 -79,98.5 -79,-98.5 ; 79,-85 79,-65 122,-65 122,-85 79,-85 ; 79,-35 79,-15 122,-15 122,-35 79,-35 ; 79,15 79,35 122,35 122,15 79,15 ; 79,65 79,85 122,85 122,65 79,65
  text "*" at -76.5,45.5 h50
Mechanical 15:
  region: -99,-107 -164,-107 -164,107 -99,107 -99,118.5 99,118.5 99,107 164,107 164,-107 99,-107 99,-118.5 -99,-118.5
  lines w6: -164,-107 -164,107 -99,107 -99,118.5 99,118.5 99,107 164,107 164,-107 99,-107 99,-118.5 -99,-118.5 -99,-107 -164,-107
3D body: height 10, standoff 0, extent 0,0 10,10
3D body "SO-8-M.step": height 69.09, standoff 0, extent -122,-98.5 122.01,98.51

## TSSOP20 [mil] "STM32 package, TSSOP20, 6.4 x 4.4mm"
pads (20):
  rect 58x14 smd paste+0 mask+0: 1(-115,115.16) 2(-115,89.57) 3(-115,63.98) 4(-115,38.39) 5(-115,12.8) 6(-115,-12.8) 7(-115,-38.39) 8(-115,-63.98) 9(-115,-89.57) 10(-115,-115.16) 11(115,-115.16) 12(115,-89.57) 13(115,-63.98) 14(115,-38.39) 15(115,-12.8) 16(115,12.8) 17(115,38.39) 18(115,63.98) 19(115,89.57) 20(115,115.16)
Top Overlay:
  region: -154,-107.66 -164,-107.66 -164,-122.66 -154,-122.66
  region: 154,122.66 164,122.66 164,107.66 154,107.66
  lines w6: -83.42,-135 83.42,-135 ; -83.42,135 83.42,135
  text "*" at -137.5,124.16 h50
Mechanical 5:
  region: 169,-155 -169,-155 -169,155 169,155
Mechanical 7:
  lines w1: -230,89.57 -115,89.57 ; -230,115.16 -115,115.16 ; -215,39.57 -215,89.57 ; -215,165.16 -215,115.16 ; -180,-205 -130,-205 ; -130,-220 -130,0 -130,295 ; -100,-220 -100,0 ; -88,0 -88,220 ; -50,-205 -100,-205 ; 0,-130 203,-130 ; 0,130 203,130 ; 88,0 88,220 ; 130,0 130,295 ; -215,89.57 -220,79.57 -210,79.57 -215,89.57 ; -215,115.16 -220,125.16 -210,125.16 -215,115.16 ; -130,-205 -140,-200 -140,-210 -130,-205 ; -130,280 130,280 ; -130,280 -120,285 -120,275 -130,280 ; -100,-205 -90,-200 -90,-210 -100,-205 ; -88,205 88,205 ; -88,205 -78,210 -78,200 -88,205 ; 88,205 78,210 78,200 88,205 ; 130,280 120,285 120,275 130,280 ; 188,-130 188,130 ; 188,-130 183,-120 193,-120 188,-130 ; 188,130 183,120 193,120 188,130
  text "Default Padstyle: RX58Y14D0T" at -350,-330 h50
  text "Pin One Padstyle: RX58Y14D0T" at -350,-390 h50
  text "Alt 1 Padstyle: OX60Y90D30P" at -337.5,-570 h50
  text "Alt 2 Padstyle: OX90Y60D30P" at -337.5,-630 h50
  text "0.176in/4.47mm" at -87.5,225 h25
  text "0.26in/6.604mm" at -87.5,300 h25
  text "0.26in/6.604mm" at 208,-12.5 h25
  text "0.026in/0.65mm" at -410,89.86 h25
  text "0.03in/0.762mm" at -202.5,-250 h25
Mechanical 13:
  lines w0: -12,130 ccw(c0,130) 12,130
  lines w1: -130,-121.16 -130,-109.16 -88,-109.16 -88,-121.16 -130,-121.16 ; -130,-95.57 -130,-83.57 -88,-83.57 -88,-95.57 -130,-95.57 ; -130,-69.98 -130,-57.98 -88,-57.98 -88,-69.98 -130,-69.98 ; -130,-44.39 -130,-32.39 -88,-32.39 -88,-44.39 -130,-44.39 ; -130,-18.8 -130,-6.8 -88,-6.8 -88,-18.8 -130,-18.8 ; -130,6.8 -130,18.8 -88,18.8 -88,6.8 -130,6.8 ; -130,32.39 -130,44.39 -88,44.39 -88,32.39 -130,32.39 ; -130,57.98 -130,69.98 -88,69.98 -88,57.98 -130,57.98 ; -130,83.57 -130,95.57 -88,95.57 -88,83.57 -130,83.57 ; -130,109.16 -130,121.16 -88,121.16 -88,109.16 -130,109.16 ; -88,-130 88,-130 88,130 -88,130 -88,-130 ; 88,-121.16 88,-109.16 130,-109.16 130,-121.16 88,-121.16 ; 88,-95.57 88,-83.57 130,-83.57 130,-95.57 88,-95.57 ; 88,-69.98 88,-57.98 130,-57.98 130,-69.98 88,-69.98 ; 88,-44.39 88,-32.39 130,-32.39 130,-44.39 88,-44.39 ; 88,-18.8 88,-6.8 130,-6.8 130,-18.8 88,-18.8 ; 88,6.8 88,18.8 130,18.8 130,6.8 88,6.8 ; 88,32.39 88,44.39 130,44.39 130,32.39 88,32.39 ; 88,57.98 88,69.98 130,69.98 130,57.98 88,57.98 ; 88,83.57 88,95.57 130,95.57 130,83.57 88,83.57 ; 88,109.16 88,121.16 130,121.16 130,109.16 88,109.16
  text "*" at -85.5,77 h50
Mechanical 15:
  region: -98,-132.16 -154,-132.16 -154,132.16 -98,132.16 -98,140 98,140 98,132.16 154,132.16 154,-132.16 98,-132.16 98,-140 -98,-140
  lines w6: -154,-132.16 -154,132.16 -98,132.16 -98,140 98,140 98,132.16 154,132.16 154,-132.16 98,-132.16 98,-140 -98,-140 -98,-132.16 -154,-132.16
3D body: height 10, standoff 0, extent 0,0 10,10
3D body "TSSOP20.step": height 47.09, standoff 0, extent -130,-130 130,130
